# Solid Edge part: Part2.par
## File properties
Author: Deepak Maini
Template: Normal.par
Last saved by: MYPC
Revision: 4
Application: Solid Edge
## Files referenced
..\Asm2.asm
7C:\solid-edge-14\c09-sldedg-14-042104\parallel\Asm2.asm
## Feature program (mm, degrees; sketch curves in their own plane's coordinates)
sketch for "unnamed Protrusion 1" plane through (0, 0, 0) normal (0, 0, 1) x-axis (1, 0, 0)
  circle centre (0, 0) radius 7
extrude "unnamed Protrusion 1" add finite 13 along +normal
sketch for "unnamed Protrusion 2" plane through (0, 0, 13) normal (0, 0, 1) x-axis (0, 1, 0)
  circle centre (0, 0) radius 8.8981
extrude "unnamed Protrusion 2" add finite 60.325 along +normal
sketch for "unnamed Protrusion 3" plane through (0, 0, 73.325) normal (0, 0, 1) x-axis (0, 1, 0)
  circle centre (0, 0) radius 7
extrude "unnamed Protrusion 3" add finite 13 along +normal
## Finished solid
Body 1: solid body, 7 faces, 6 edges, 0 vertices.
  Faces by surface: plane 4, cylinder 3
  Edges by curve: circle 6
Bounding box of the edges (mm): 17.796 x 17.796 x 86.325, from (-8.8981, -8.8981, 0) to (8.8981, 8.8981, 86.325).
Cylindrical faces by radius (mm): R7 x2, R8.8981 x1
Planar faces by outward normal: +z 2, -z 2
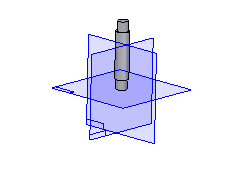
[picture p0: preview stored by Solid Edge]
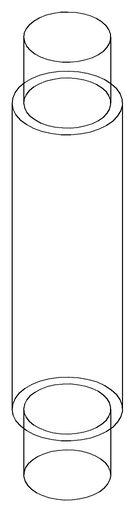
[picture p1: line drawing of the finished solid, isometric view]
